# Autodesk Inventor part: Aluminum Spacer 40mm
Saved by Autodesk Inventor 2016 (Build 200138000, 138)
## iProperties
Created: 2016-03
Part Number: Aluminum Spacer 40mm
Material: Generic
Document SubType Name: Modeling
Designer: bongo_000
Density: 1 g/cm^3
Appearance: Default
Author: bongo_000
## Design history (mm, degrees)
feature "CHAMFER1"
body "Solid1"
